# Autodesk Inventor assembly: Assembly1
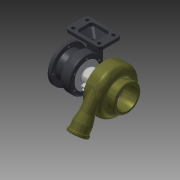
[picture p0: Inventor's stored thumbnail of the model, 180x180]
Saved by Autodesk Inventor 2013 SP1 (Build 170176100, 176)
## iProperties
Created: 2013-05
Part Number: Assembly1
Document SubType Name: Assembly
Designer: 50384
Author: 50384
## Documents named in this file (7)
- \\172.24.3.4\2013\50384\Adv E\Turbo\Inventor\Assembly1.iam
- \\172.24.3.4\2013\50384\Adv E\Turbo\Inventor\5.ipt
- \\172.24.3.4\2013\50384\Adv E\Turbo\Inventor\6.ipt
- \\172.24.3.4\2013\50384\Adv E\Turbo\Inventor\7.ipt
- \\172.24.3.4\2013\50384\Adv E\Turbo\Inventor\8.ipt
- \\172.24.3.4\2013\50384\Adv E\Turbo\Inventor\4.ipt
- \\172.24.3.4\2013\50384\Adv E\Turbo\Inventor\3.ipt
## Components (6 placed, 6 different names)
1. 5:1 — Mate:1, Mate:2, Mate:3, Mate:4, Mate:5, Mate:6, Mate:7
2. 6:1 — Mate:6, Mate:7
3. 7:1 — Mate:8, Mate:9
4. 8:1 — Mate:10, Mate:11
5. 4:1 — Mate:1, Mate:2
6. 3:1 — Mate:3, Mate:4, Mate:5, Mate:8, Mate:9, Mate:10, Mate:11
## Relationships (11: Mate 11)
- Mate:1: 5:1 ↔ 4:1
- Mate:2: 5:1 ↔ 4:1
- Mate:3: 5:1 ↔ 3:1
- Mate:4: 5:1 ↔ 3:1
- Mate:5: 5:1 ↔ 3:1
- Mate:6: 5:1 ↔ 6:1
- Mate:7: 5:1 ↔ 6:1
- Mate:8: 7:1 ↔ 3:1
- Mate:9: 7:1 ↔ 3:1
- Mate:10: 8:1 ↔ 3:1
- Mate:11: 8:1 ↔ 3:1
